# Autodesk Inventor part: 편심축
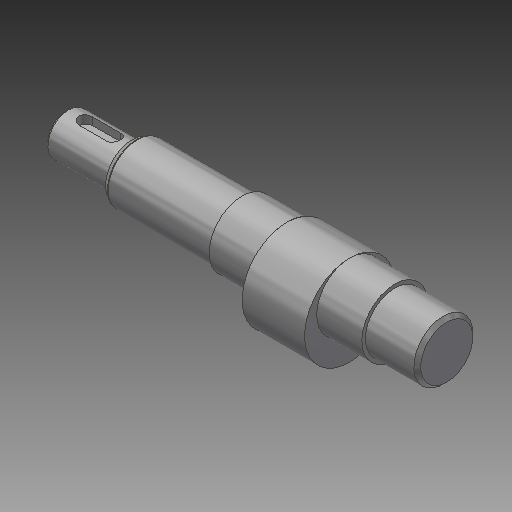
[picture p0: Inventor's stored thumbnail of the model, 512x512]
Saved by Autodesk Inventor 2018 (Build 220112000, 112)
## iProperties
Created: 2017-08
Part Number: 편심축
Material: 강철, 연강
Document SubType Name: Modeling
Designer: mduedu
Density: 1 g/cm^3
Appearance: 강철
Author: mduedu
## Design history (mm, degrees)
sketch "스케치1"
  geometry: L1 (0, 0)-(110, 0); L2 (110, 0)-(110, 8.5); L3 (110, 8.5)-(95, 8.5); L4 (95, 8.5)-(95, 9.5); L5 (95, 9.5)-(51, 9.5); L6 (51, 9.5)-(51, 8.5); L7 (51, 8.5)-(19, 8.5); L8 (19, 8.5)-(19, 6); L9 (19, 6)-(0, 6); L10 (0, 6)-(0, 0)
  constraints: 20 end point, 6 parallel, 2 collinear, 2 perpendicular, 1 horizontal
  dimensions: "d0" = 110 distance of L1.start L1.end; "d1" = 17 diameter of L3 L1; "d2" = 19 diameter of L5 L1; "d3" = 12 diameter of L9 L1; "d4" = 19 distance of L8.end L9.end; "d5" = 15 distance of L2.end L3.end; "d6" = 44 distance of L4.end L5.end
revolve "회전1" sketch "스케치1" stored, may be unused: angle "d7" = 90 deg
node "작업 평면1"
sketch "스케치2"
  geometry: C1 r 9.5 at (0, 0) reference; C2 r 13 at (0, -3.5); 1 further point
  constraints: 1 centre point, 1 tangent, 1 vertical alignment
  dimensions: "d8" = 3.5 distance of point (0, 0) C2.centre
extrude "돌출1" join sketch "스케치2" stored distance "d9" = 18; taper "d10" = 0 deg
chamfer "모따기1" distance "d11" = 1; stored, may be unused: second distance "d12" = 2, angle "d13" = 45 deg
node "작업 평면2"
sketch "스케치3"
  geometry: L1 (3.5, -2)-(-4.5, -2); L2 (-4.5, -2)-(-4.5, 2); L3 (-4.5, 2)-(3.5, 2); L4 (3.5, 2)-(3.5, -2); L5 (9.5, 6)-(9.5, -6) reference; A1 r 2 centre (3.5, 0) between (3.5, -2) and (3.5, 2); A2 r 2 centre (-4.5, 0) between (-4.5, 2) and (-4.5, -2); A3 r 2 centre (3.5, 0) between (3.5, 2) and (3.5, -2); A4 r 2 centre (-4.5, 0) between (-4.5, -2) and (-4.5, 2); 1 further point
  constraints: 8 end point, 8 point on circle, 4 centre point, 2 midpoint, 2 parallel, 1 horizontal, 1 horizontal alignment, 1 perpendicular
  dimensions: "d14" = 12 dimension on A2 A1; "d16" = 4 distance between parallel lines of L3 L1; "d17" = 4 distance edge to line of A1 L5
extrude "돌출2" cut sketch "스케치3" distance "d18" = 2.5; taper "d19" = 0 deg
chamfer "모따기2" distance "d20" = 1; stored, may be unused: second distance "d21" = 2, angle "d22" = 45 deg
chamfer "모따기3" distance "d23" = 1; stored, may be unused: second distance "d24" = 2, angle "d25" = 60 deg
fillet "모깎기1" dims "d26" = 0.5
hole "구멍1" diameter "d29" = 3.242; stored, may be unused: countersink angle "d33" = 90 deg, drill point angle "d35" = 118 deg; dims "d30" = 8, "d31" = 4, "d32" = 2, "d34" = 10, "d36" = 10, "d37" = 10
node "솔리드1"
node "절단 모서리 투영1"
